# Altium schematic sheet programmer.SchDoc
size A3
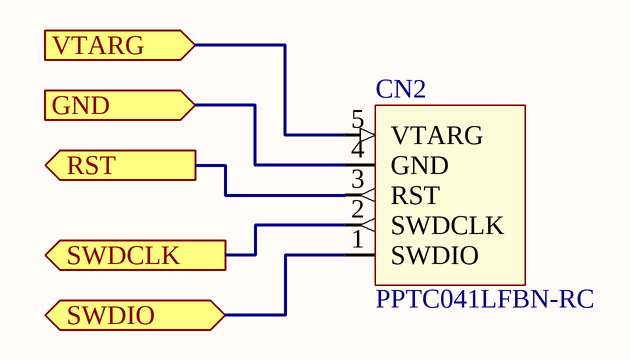
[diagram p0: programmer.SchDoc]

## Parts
CN2  PPTC041LFBN-RC  [PR20203VBNN-Footprint-1]

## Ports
GND (in), RST (out), SWDCLK (out), SWDIO (bidir), VTARG (in)

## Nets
GND: CN2.4(GND) ; port GND
RST: CN2.3(RST) ; port RST
SWDCLK: CN2.2(SWDCLK) ; port SWDCLK
SWDIO: CN2.1(SWDIO) ; port SWDIO
VTARG: CN2.5(VTARG) ; port VTARG

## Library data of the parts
CN2 = CMP-ROOT-00017-7: CONN HDR 5POS 0.1 GOLD PCB used for connecting to cypress kitprog_usb; Pitch: 0.1inch; System: Connector; Connector Type: Header,Socket; Number of Positions: 5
